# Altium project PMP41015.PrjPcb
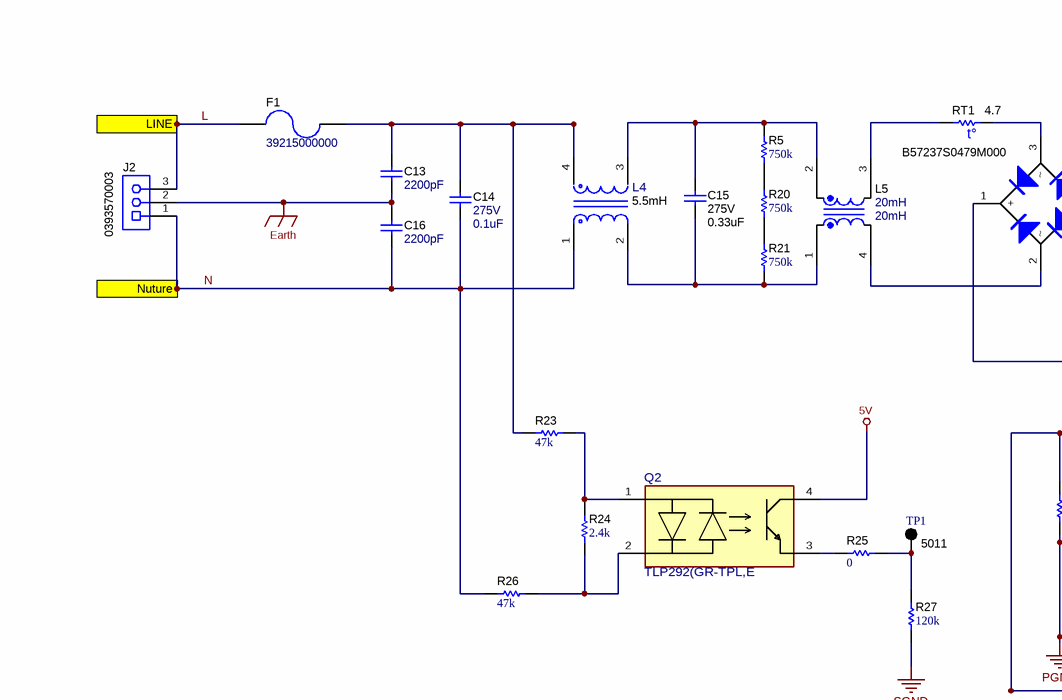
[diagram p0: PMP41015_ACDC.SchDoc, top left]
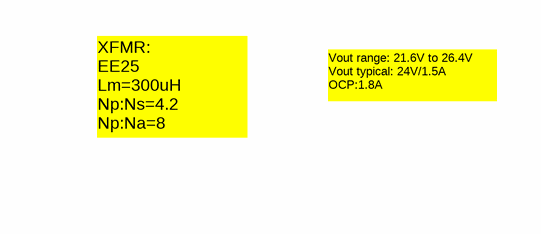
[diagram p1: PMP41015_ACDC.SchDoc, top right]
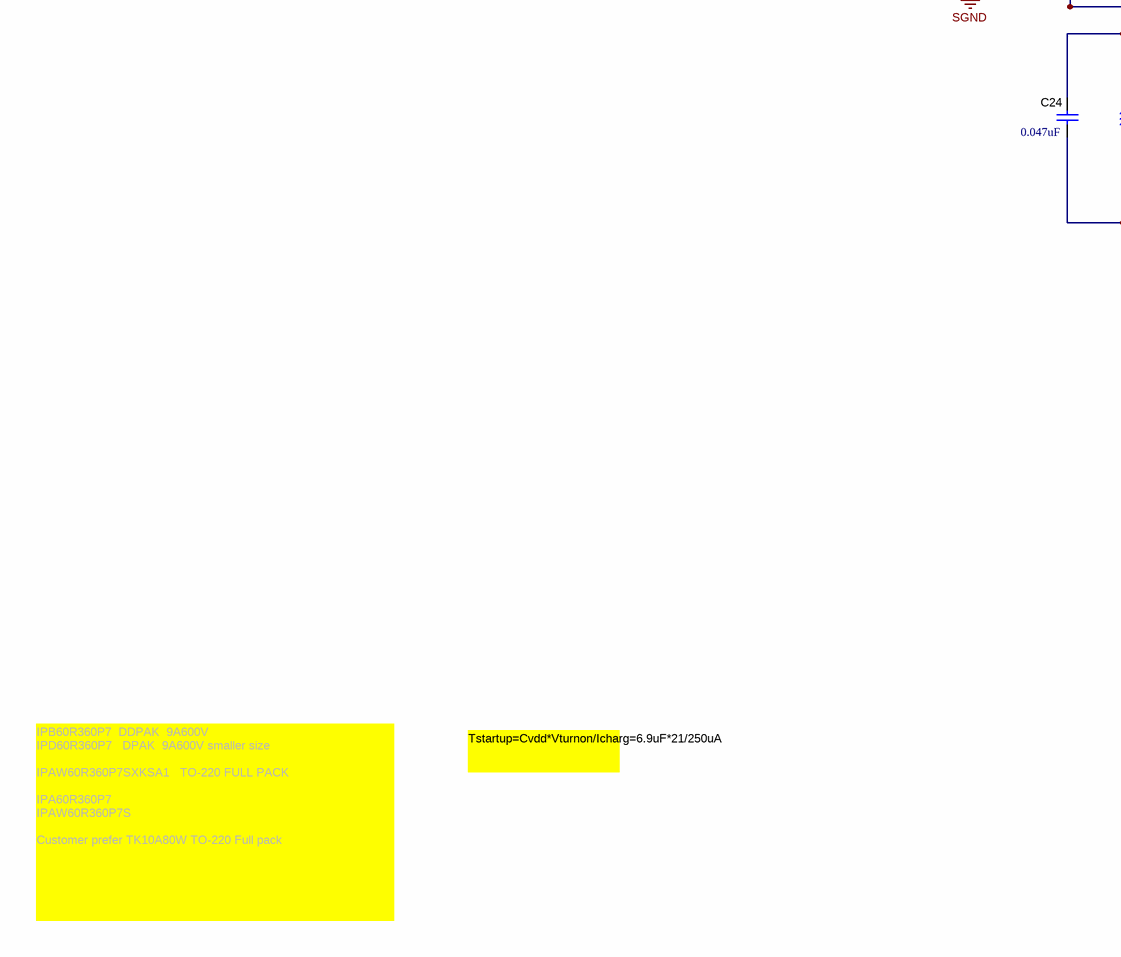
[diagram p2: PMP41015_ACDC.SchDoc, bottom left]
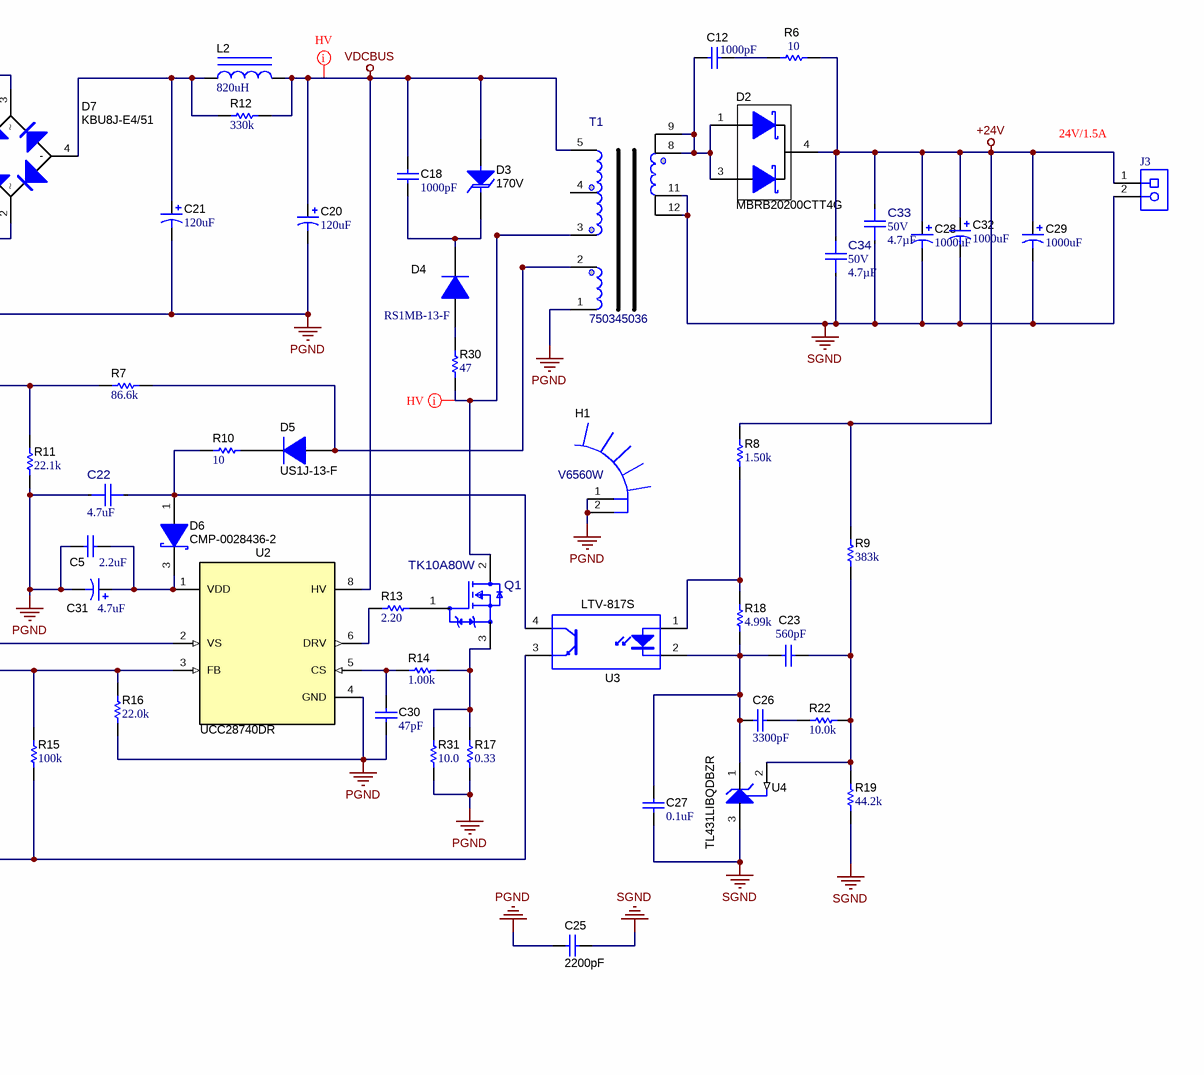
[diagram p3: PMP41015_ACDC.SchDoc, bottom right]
CopyrightYear: 2018; PCB_Layout: Max Wang; PCB_Rev: E1; PRJ_Customer: Public Release; PRJ_Engineer: Max Wang; PRJ_Number: PMP41015; PRJ_Title: PMP41015; SCH_Rev: E1; TechSupport: http://www.ti.com/support; TID: N/A
2 sheets, 89 parts. Net scope: flat (ports and power ports of the same name join across sheets).
Board file: PMP41015.PcbDoc
Sheets:
  PMP41015_ACDC.SchDoc
  PMP41015_DCDC.SchDoc

## Sheet PMP41015_ACDC.SchDoc
size 431 x 279 mm; Date: Not shown in title block; ApprovedBy: Not shown in title block; CheckedBy: Not shown in title block; Author: Max Wang; CompanyName: Not shown in title block; DrawnBy: Max Wang; Engineer: Not shown in title block; Organization: Not shown in title block; Address1: Not shown in title block; Address2: Not shown in title block; Address3: Not shown in title block; Address4: Not shown in title block; DocumentNumber: 2; Revision: Use project parameter SCH_Rev; SheetNumber: 1; SheetTotal: 2; PageSetup: Record=PageOptions¦CenterHorizontal=True¦CenterVertical=True¦PrintScale=1.00¦XCorrection=1.00¦YCorrection=1.00¦PrintKind=0¦BorderSize=5000000¦LeftOffset=0¦BottomOffset=0¦Orientation=2¦PaperLength=1000¦PaperWidth=1000¦Scale=100¦PaperSource=15¦PrintQuality=600¦MediaType=1¦DitherType=10¦PaperKind=Letter¦PrintScaleMode=1

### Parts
C5  ValueDisplayed: 2.2uF  [0805_HV]  (hidden comment: C2012X7R1H225K125AC)
C12  ValueDisplayed: 1000pF  [0805_HV]  (hidden comment: CMP-0007712-2)
C13  ValueDisplayed: 2200pF  [VY2_900x500_5]  (hidden comment: VY2222M35Y5UG6TV5)
C14  VDC_V: 275V  ValueDisplayed: 0.1uF  [CAPRR1500W60L1750T550H1250]  (hidden comment: ECQ-U2A104ML)
C15  VDC_V: 275V  ValueDisplayed: 0.33uF  [CAPRR1500W80L1750T950H1750]  (hidden comment: ECQ-U2A334ML)
C16  ValueDisplayed: 2200pF  [VY2_900x500_5]  (hidden comment: VY2222M35Y5UG6TV5)
C18  ValueDisplayed: 1000pF  [1206]  (hidden comment: CMP-0008891-2)
C20  ValueDisplayed: 120uF  [Nichicon_2500x3000_Snap]  (hidden comment: CMP-0010099-2)
C21  ValueDisplayed: 120uF  [Nichicon_2500x3000_Snap]  (hidden comment: CMP-0010099-2)
C22  ValueDisplayed: 4.7uF  [FP-CGA4J1X7R1H475K125AC_0805-MFG]  (hidden comment: CGA4J1X7R1H475K125AC)
C23  ValueDisplayed: 560pF  [0603]  (hidden comment: 06035C561KAT2A)
C24  ValueDisplayed: 0.047uF  [0603]  (hidden comment: CMP-0007015-5)
C25  ValueDisplayed: 2200pF  [CD45_900x600x1300]  (hidden comment: CD45-E2GA222M-NKA)
C26  ValueDisplayed: 3300pF  [0603]  (hidden comment: C0603C332F5GACTU)
C27  ValueDisplayed: 0.1uF  [0603]  (hidden comment: CMP-0006752-5)
C28  ValueDisplayed: 1000uF  [Chemi-Con_1250x2000]  (hidden comment: ELXZ350ELL102MK25S)
C29  ValueDisplayed: 1000uF  [Chemi-Con_1250x2000]  (hidden comment: ELXZ350ELL102MK25S)
C30  ValueDisplayed: 47pF  [0603]  (hidden comment: CMP-0006939-4)
C31  ValueDisplayed: 4.7uF  [SM_RADIAL_5MM]  (hidden comment: CMP-0011424-2)
C32  ValueDisplayed: 1000uF  [Chemi-Con_1250x2000]  (hidden comment: ELXZ350ELL102MK25S)
C33  VDC_V: 50V  Cap_F: 4.7µF  [FP-C2012X7R1H475K125AC_0805-MFG]  (hidden comment: C2012X7R1H475K125AC)
C34  VDC_V: 50V  Cap_F: 4.7µF  [FP-C2012X7R1H475K125AC_0805-MFG]  (hidden comment: C2012X7R1H475K125AC)
D2  MBRB20200CTT4G  [DDPAK]
D3  value 170V  [SMB]  (hidden comment: CMP-0005579-3)
D4  PartNumber: RS1MB-13-F  [SMB]  (hidden comment: CMP-0076889-2)
D5  US1J-13-F  [SMA]
D6  CMP-0028436-2  [SOT-23]
D7  KBU8J-E4/51  [KBU]
F1  39215000000  [FUSE_392]
H1  V6560W  [HSINK_V6560W]
J2  0393570003  [MOLEX_39357-0003]
J3  0393570002  [MOLEX_39357-0002]  (value not drawn)
L2  ValueDisplayed: 820uH  [WE-PD_1210]  (hidden comment: 7447709821)
L4  Ind_H: 5.5mH  [FP-750343092_PTH_14MM0_8MM89-0]  (hidden comment: 750343092)
L5  value 20mH  [WE-CMB_M]  (hidden comment: 744823220)
Q1  TK10A80W  [FP-IPAW60R360P7SXKSA1_PG-TO220-3-MFG]
Q2  TLP292(GR-TPL,E  [FP-TLP292(GR-TPL,E_SO4-IPC_A]
R5  ValueDisplayed: 750k  [1206]  (hidden comment: CMP-0017156-3)
R6  ValueDisplayed: 10  [0805_HV]  (hidden comment: CMP-0020804-2)
R7  ValueDisplayed: 86.6k  [0603]  (hidden comment: CMP-0022628-4)
R8  ValueDisplayed: 1.50k  [0603]  (hidden comment: CMP-0022883-5)
R9  ValueDisplayed: 383k  [0603]  (hidden comment: CMP-0024170-3)
R10  ValueDisplayed: 10  [0603]  (hidden comment: CMP-0025703-4)
R11  ValueDisplayed: 22.1k  [0603]  (hidden comment: CMP-0022220-4)
R12  ValueDisplayed: 330k  [1206]  (hidden comment: CMP-0018656-3)
R13  ValueDisplayed: 2.20  [0603]  (hidden comment: ERJ-3RQF2R2V)
R14  ValueDisplayed: 1.00k  [0603]  (hidden comment: CMP-0022109-5)
R15  ValueDisplayed: 100k  [0603]  (hidden comment: CMP-0022735-5)
R16  ValueDisplayed: 22.0k  [0603]  (hidden comment: CMP-0022925-5)
R17  ValueDisplayed: 0.33  [1206]  (hidden comment: CMP-0017788-3)
R18  ValueDisplayed: 4.99k  [0603]  (hidden comment: CMP-0023354-3)
R19  ValueDisplayed: 44.2k  [0603]  (hidden comment: CMP-0023118-5)
R20  ValueDisplayed: 750k  [1206]  (hidden comment: CMP-0017156-3)
R21  ValueDisplayed: 750k  [1206]  (hidden comment: CMP-0017156-3)
R22  ValueDisplayed: 10.0k  [0603]  (hidden comment: CMP-0021998-4)
R23  ValueDisplayed: 47k  [PR02]  (hidden comment: CMP-0014401-2)
R24  ValueDisplayed: 2.4k  [0402]  (hidden comment: CMP-0026891-5)
R25  ValueDisplayed: 0  [0603]  (hidden comment: CMP-0025697-4)
R26  ValueDisplayed: 47k  [PR02]  (hidden comment: CMP-0014401-2)
R27  ValueDisplayed: 120k  [0402]  (hidden comment: CMP-0025983-3)
R30  ValueDisplayed: 47  [1206]  (hidden comment: CMP-0018687-3)
R31  ValueDisplayed: 10.0  [0805_HV]  (hidden comment: CMP-0020847-3)
RT1  B57237S0479M000  value 4.7  [S237]
T1  750345036  [EE28 from Customer]
TP1  5011  [Keystone5011]
U2  UCC28740DR  [D0007A_N]
U3  LTV-817S  [DIP254P762X350-4]
U4  TL431LIBQDBZR  [DBZ0003A_N]

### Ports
LINE (in), Nuture (in)

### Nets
5V: Q2.4(Collector)
+24V: C28.1(+) C29.1(+) C32.1(+) C33.2 C34.2 D2.4(K) J3.1 R6.2 R8.2 R9.2
Earth: C13.2 C16.1 J2.2
PGND: C5.2 C20.2(-) C21.2(-) C22.1 C25.1 C30.2 C31.2(-) D7.1(+) H1.1 H1.2 R11.1 R16.1 R17.1 R31.1 T1.1 U2.4(GND)
SGND: C25.2 C27.2 C28.2(-) C29.2(-) C32.2(-) C33.1 C34.1 J3.2 R19.1 R27.1 T1.11 T1.12 U4.3(ANODE)
VDCBUS: C18.1 C20.1(+) D3.2(A) L2.2 R12.2 T1.5 U2.8(HV)
L: F1.2 J2.3 ; port LINE
N: C14.2 C16.2 J2.1 L4.1 R26.1 ; port Nuture
NetC5_1: C5.1 C31.1(+) D6.3(K) U2.1(VDD)
NetC12_1: C12.1 D2.1(A) D2.3(A) T1.8 T1.9
NetC12_2: C12.2 R6.1
NetC13_1: C13.1 C14.1 F1.1 L4.4 R23.1
NetC15_1: C15.1 L4.3 L5.2 R5.2
NetC15_2: C15.2 L4.2 L5.1 R21.1
NetC18_2: C18.2 D3.1(K) D4.1(K)
NetC21_1: C21.1(+) D7.4(-) L2.1 R12.1
NetC22_2: C22.2 D6.1(A) R10.1 U3.4(C)
NetC23_1: C23.1 R9.1 R19.2 R22.2 U4.2(REF)
NetC23_2: C23.2 C26.2 C27.1 R18.1 U3.2(K) U4.1(CATHODE)
NetC24_1: C24.1 R15.2 R16.2 U2.3(FB)
NetC24_2: C24.2 R15.1 U3.3(E)
NetC26_1: C26.1 R22.1
NetC30_1: C30.1 R14.1 U2.5(CS)
NetD4_2: D4.2(A) R30.2
NetD5_1: D5.1(K) R10.2
NetD5_2: D5.2(A) R7.2 T1.2
NetD7_2: D7.2 L5.4
NetD7_3: D7.3 RT1.2
NetL5_3: L5.3 RT1.1
NetQ1_1: Q1.1(Gate) R13.2
NetQ1_2: Q1.2(Drain) R30.1 T1.3
NetQ1_3: Q1.3(Source) R14.2 R17.2 R31.2
NetQ2_1: Q2.1(Anode/Cathode) R23.2 R24.2
NetQ2_2: Q2.2(Cathode/Anode) R24.1 R26.2
NetQ2_3: Q2.3(Emitter) R25.1
NetR5_1: R5.1 R20.2
NetR7_1: R7.1 R11.2 U2.2(VS)
NetR8_1: R8.1 R18.2 U3.1(A)
NetR13_1: R13.1 U2.6(DRV)
NetR20_1: R20.1 R21.2
NetR25_2: R25.2 R27.2 TP1.1

Not connected (* = marked no-connect by the designer): T1 4

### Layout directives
net class HV BUS: NetQ1_2, VDCBUS

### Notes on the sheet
- Vout range: 21.6V to 26.4V
  Vout typical: 24V/1.5A
  OCP:1.8A
- XFMR:
  EE25
  Lm=300uH
  Np:Ns=4.2
  Np:Na=8
- (near J3) 24V/1.5A
- Tstartup=Cvdd*Vturnon/Icharg=6.9uF*21/250uA
- IPB60R360P7  DDPAK  9A600V
  IPD60R360P7   DPAK  9A600V smaller size
  IPAW60R360P7SXKSA1   TO-220 FULL PACK
  IPA60R360P7
  IPAW60R360P7S
  Customer prefer TK10A80W TO-220 Full pack

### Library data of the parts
C5 = CMP-0007877-2: CAP, CERM, 2.2 uF, 50 V, +/- 10%, X7R, 0805; Manufacturer: TDK; Polarized: N; Value: 2.2uF; U/M: EA; Cap_F: 2.2µF; ESR_ohm: 3.66m; Value1: 0.00366 ohm; VDC_V: 50V; IRMS_A: 3.4121A; TaMin_C: -55°C; TaMax_C: 125°C; Cap_Case: 0805; SizeArea_mm2: 2.5; SizeAreaWB_mm2: 6.75; SizeX_mm: 2; SizeY_mm: 1.25; SizeZ_mm: 1.45; AEC Category: Q200
C12 = CMP-0007712-2: CAP, CERM, 1000 pF, 630 V, +/- 5%, X7R, 0805; PartNumber: C0805C102JBRACTU; Manufacturer: Kemet; Polarized: N; Value: 1000pF; U/M: EA; Cap_F: 1nF; Value1: Unknown; VDC_V: 630V; TaMin_C: -55°C; TaMax_C: 125°C; Cap_Case: 0805; SizeArea_mm2: 2.5; SizeAreaWB_mm2: 6.75; SizeX_mm: 2; SizeY_mm: 1.25; SizeZ_mm: 1.45; AEC Category: Q200
C13 C16 = CMP-0080613-1: CAP, CERM, 2200 pF, X1 440 VAC/Y2 300 VAC, +/- 20%, Y5U, Body9x5mm; Manufacturer: Vishay-Bccomponents; TaMin_C: -40°C; Polarized: N; AC_Safety: X1Y2; SizeAreaWB_mm2: 77; U/M: EA; Value: 2200pF; TaMax_C: 125°C; VAC_Y: 300V; VAC_X: 440V; SizeZ_mm: 13; SizeX_mm: 9; SizeY_mm: 5; Cap_Case: 9x5mm; SizeArea_mm2: 45; Cap_F: 2.2nF; AEC Category: Q200
C14 = CMP-0012496-1: CAP, Film, 0.1 uF, 275 V, +/- 20%, TH; Manufacturer: Panasonic; TaMin_C: -40°C; Polarized: N; Value1: Unknown; U/M: EA; Value: 0.1uF; TaMax_C: 100°C; Cap_Case: Radial 17.5x5.5x12.5; Cap_F: 100nF; AEC Category: Q200
C15 = CMP-0012499-3: CAP, Film, 0.33 uF, 275 V, +/- 20%, TH; Manufacturer: Panasonic; TaMin_C: -40°C; Polarized: N; SizeAreaWB_mm2: 224.25; Value1: Unknown; Value: 0.33uF; TaMax_C: 100°C; SizeZ_mm: 18; SizeX_mm: 17.5; SizeY_mm: 9.5; Cap_Case: Radial,17.5x17.5x9.5mm; SizeArea_mm2: 166.25; Cap_F: 330nF; AEC Category: Q200
C18 = CMP-0008891-2: CAP, CERM, 1000 pF, 630 V, +/- 5%, U2J, 1206; PartNumber: GRM31A7U2J102JW31D; Manufacturer: MuRata; Polarized: N; Value: 1000pF; U/M: EA; Cap_F: 1nF; Value1: Unknown; VDC_V: 630V; TaMin_C: -55°C; TaMax_C: 125°C; SizeArea_mm2: 5.12; SizeAreaWB_mm2: 10.92; SizeX_mm: 3.2; SizeY_mm: 1.6; SizeZ_mm: 1.35; AEC Category: Q200
C20 C21 = CMP-0010099-2: CAP, AL, 120 uF, 450 V, +/- 20%, TH; PartNumber: LLS2W121MELA; Manufacturer: Nichicon; Polarized: Y; CompType: Capacitor; Value: 120uF; U/M: EA; Cap_F: 120µF; Value1: Unknown; VDC_V: 450V; IRMS_A: 1.09A; TaMin_C: -25°C; TaMax_C: 85°C; Cap_Case: 25x30mm; SizeAreaWB_mm2: 729; SizeArea_mm2: 625; SizeX_mm: 25; SizeZ_mm: 32; AEC Category: Q200; AEC Qualified: N
C22 = CMP-0090082-1: Cap Ceramic 4.7uF 50V X7R 10% Pad SMD 0805 +125°C Automotive T/R; Manufacturer: TDK Corporation; Value: 4.7µF; Tolerance_%: 0.1%; TempCo: 15%; SizeZ_mm: 1.45mm; AEC Qualified: Yes; AEC Grade: Grade 1
C23 = CMP-0006807-4: CAP, CERM, 560 pF, 50 V, +/- 10%, X7R, 0603; Manufacturer: AVX; Polarized: N; Value: 560pF; U/M: EA; Value1: Unknown; VDC_V: 50V; TaMin_C: -55°C; TaMax_C: 125°C; SizeArea_mm2: 1.28; SizeAreaWB_mm2: 4.68; SizeX_mm: 1.6; SizeY_mm: 0.8; SizeZ_mm: 1; AEC Category: Q200
C24 = CMP-0007015-5: CAP, CERM, 0.047 uF, 50 V, +/- 10%, X5R, 0603; PartNumber: C1608X5R1H473K080AA; Manufacturer: TDK; Polarized: N; U/M: EA; Cap_F: 47nF; ESR_ohm: 49.007m; Value1: 0.049007 ohm; VDC_V: 50V; IRMS_A: 767.528mA; TaMin_C: -55°C; TaMax_C: 85°C; SizeArea_mm2: 1.28; SizeAreaWB_mm2: 4.68; SizeX_mm: 1.6; SizeY_mm: 0.8; SizeZ_mm: 1; AEC Category: Q200
C25 = CMP-0009597-2: CAP, CERM, 2200 pF,  V, +/- 20%, E, D9xT6mm; Manufacturer: TDK; TaMin_C: -25°C; Polarized: N; SizeAreaWB_mm2: 101.2; Value1: Unknown; U/M: EA; Value: 2200pF; TaMax_C: 125°C; SizeZ_mm: 13; SizeX_mm: 10.65; SizeY_mm: 6; Cap_Case: 9x6x13mm; SizeArea_mm2: 63.9; Cap_F: 2.2nF; AEC Category: Q200
C26 = CMP-0081060-1: CAP, CERM, 3300 pF, 50 V,+/- 1%, C0G/NP0, 0603; Manufacturer: Kemet; Polarized: N; Value: 3300pF; U/M: EA; Cap_F: 3.3nF; VDC_V: 50V; TaMin_C: -55°C; TaMax_C: 125°C; SizeArea_mm2: 1.28; SizeAreaWB_mm2: 4.68; SizeX_mm: 1.6; SizeY_mm: 0.8; SizeZ_mm: 1; AEC Category: Q200; Green_Lifecycle: Active; Green_REACh: Passed
C27 = CMP-0006752-5: CAP, CERM, 0.1 uF, 25 V, +/- 5%, X7R, 0603; PartNumber: 06033C104JAT2A; Manufacturer: AVX; Polarized: N; Value: 0.1uF; U/M: EA; Cap_F: 100nF; ESR_ohm: 50m; Value1: 0.05 ohm; VDC_V: 25V; TaMin_C: -55°C; TaMax_C: 125°C; SizeArea_mm2: 1.28; SizeAreaWB_mm2: 4.68; SizeX_mm: 1.6; SizeY_mm: 0.8; SizeZ_mm: 1; AEC Category: Q200
C28 C29 C32 = CMP-0010484-2: CAP, AL, 1000 uF, 35 V, +/- 20%, AEC-Q200 Grade 2, TH; Manufacturer: Chemi-Con; Polarized: Y; CompType: Capacitor; Value: 1000uF; U/M: EA; Cap_F: 1mF; Value1: Unknown; VDC_V: 35V; IRMS_A: 1.95A; TaMin_C: -55°C; TaMax_C: 105°C; Cap_Case: 12.5x25mm; SizeAreaWB_mm2: 210.25; SizeArea_mm2: 156.25; SizeX_mm: 12.5; SizeZ_mm: 21.5; AEC Category: Q200; AEC Grade: 2
C30 = CMP-0006939-4: CAP, CERM, 47 pF, 50 V, +/- 5%, C0G/NP0, 0603; PartNumber: C0603C470J5GACTU; Manufacturer: Kemet; Polarized: N; Value: 47pF; U/M: EA; Value1: Unknown; VDC_V: 50V; TaMin_C: -55°C; TaMax_C: 125°C; SizeArea_mm2: 1.28; SizeAreaWB_mm2: 4.68; SizeX_mm: 1.6; SizeY_mm: 0.8; SizeZ_mm: 1; AEC Category: Q200
C31 = CMP-0011424-2: CAP, AL, 4.7 uF, 50 V, +/- 20%, 1.52 ohm, SMD; PartNumber: UUD1H4R7MCL1GS; Manufacturer: Nichicon; Polarized: Y; CompType: Capacitor; Value: 4.7uF; U/M: EA; Cap_F: 4.7µF; VDC_V: 50V; ESR_ohm: 1.52; IRMS_A: 85mA; TaMin_C: -55°C; TaMax_C: 105°C; Cap_Case: 5x5.8; SizeAreaWB_mm2: 58.4; SizeArea_mm2: 31.8; SizeX_mm: 6; SizeY_mm: 5.3; AEC Category: Q200
C33 C34 = CMP-0088943-1: 4.7µF ±10% 50V Ceramic Capacitor X7R 0805 (2012 Metric); Manufacturer: TDK; TempCo: 15%; AEC Qualified: No; ValueDisplayed: 4.7uF; SizeZ_mm: 1.5mm
D2 = CMP-0028500-1: Diode, Schottky, 200 V, 20 A, DDPAK; Manufacturer: ON Semiconductor; Io_A: 20A; Green_Lifecycle: Not Set; SizeAreaWB_mm2: 209.6992; Vr_V: 200V; Green_REACh: Incomplete; TJmax_C: 150°C; U/M: EA; Value: 200V; SizeZ_mm: 4.445; SizeX_mm: 15.245; SizeY_mm: 10.16; Vf_V: 1V; SizeArea_mm2: 154.8892; AEC Category: Q101; RJC_CperW: 2
D3 = CMP-0005579-3: Diode, TVS, Uni, 170 V, 275 Vc, SMB; PartNumber: SMBJ170A-13-F; Manufacturer: Diodes Inc.; Value1: 600W; SizeAreaWB_mm2: 44.156; SizeArea_mm2: 21.336; SizeX_mm: 5.6; SizeY_mm: 3.81; SizeZ_mm: 2.6; AEC Category: Q101; Vbr_Min: 189V; Vc: 275V; Ipp: 2.2A; Vbr_Max: 217.5V
D4 = CMP-0076889-2: Diode, P-N, 1000 V, 1 A, SMB; Manufacturer: Diodes Inc.; Vf_V: 1.3V; Value: 1000V; Value1: 1A; Vr_V: 1kV; TJmax_C: 150°C; RJC_CperW: 20.0; SizeAreaWB_mm2: 44.156; SizeArea_mm2: 21.336; SizeX_mm: 5.6; SizeY_mm: 3.81; SizeZ_mm: 2.6; AEC Category: Q101; Green_Lifecycle: Active; Green_REACh: Passed
D5 = CMP-0077027-2: Diode, Ultrafast, 600 V, 1 A, SMA; Manufacturer: Diodes Inc.; Vf_V: 1.7V; Value: 600V; Value1: 1A; TJmax_C: 150°C; SizeAreaWB_mm2: 37.3428; SizeArea_mm2: 16.3228; SizeX_mm: 5.59; SizeY_mm: 2.92; SizeZ_mm: 2.87; AEC Category: Q101; Green_Lifecycle: Active; Green_REACh: Passed
D6 = CMP-0028436-2: Diode, Schottky, 40 V, 0.2 A, SOT-23; PartNumber: BAS40-7-F; Manufacturer: Diodes Inc.; Vf_V: 800mV; Value: 40V; Value1: 0.2A; Value2: 0.8V; Io_A: 200mA; SizeAreaWB_mm2: 14; SizeArea_mm2: 7.5; SizeX_mm: 2.5; SizeY_mm: 3; SizeZ_mm: 1.1; AEC Category: Q101; Green_Lifecycle: Not Set; Green_REACh: Incomplete
D7 = CMP-0085999-1: Diode, Switching-Bridge, 600 V, 8 A, TH; Manufacturer: Vishay-Semiconductor; Value2: 1V; SizeX_mm: 23.2; SizeAreaWB_mm2: 223.02; SizeY_mm: 6.85; SizeZ_mm: 19.3; Value1: 8A; AEC Qualified: N; AEC Category: Q101; TJmax_C: 150°C; Vr_V: 600V; Value: 600V; SizeArea_mm2: 158.92
F1 = CMP-0003562-2: Fuse, 5 A, 250VAC/VDC, TH; Manufacturer: Littelfuse; Irating_A: 5A; VAC_V: 250V
H1 = CMP-0086362-1: Heat Sink TO-220; Manufacturer: Assman WSW
J2 = CMP-0055340-2: Terminal Block, 3.5 mm, 3x1, Tin, TH; Manufacturer: Molex; Green_Lifecycle: Not Set; Green_REACh: Incomplete; CNHeader: FALSE; CT: TRUE
J3 = CMP-0055341-2: Terminal Block, 3.5 mm, 2x1, Tin, TH; Manufacturer: Molex; Green_Lifecycle: Not Set; Green_REACh: Incomplete; CNHeader: FALSE; CT: TRUE
L2 = CMP-0064762-2: Inductor, Shielded Drum Core, Ferrite, 820 uH, 0.95 A, 1 ohm, SMD; Manufacturer: Wurth Elektronik; Isat: 1.1A @ 10% inductance drop; Irms: 0.95A @ 40C rise; Green_Lifecycle: Active; SizeAreaWB_mm2: 196; DCR_ohm: 1; Green_REACh: Passed; Value1: 1 ohm; Value: 820uH; Imax_A: 950mA; SizeZ_mm: 10; SizeX_mm: 12; Value2: 0.95A; SizeArea_mm2: 144; Ind_H: 820µH; AEC Category: Q200
L4 = CMP-0086690-2: Power Common Mode Choke; Manufacturer: Wurth Electronics; SizeZ_mm: 18.5mm; DCR_ohm: 0.04; AEC Qualified: No
L5 = CMP-0013122-1: Coupled inductor, 20 mH, 1.5 A, 0.27 ohm, TH; Manufacturer: Wurth Elektronik; SizeAreaWB_mm2: 513; DCR_ohm: 0.27; SizeZ_mm: 26.5; SizeX_mm: 25; SizeY_mm: 17; SizeArea_mm2: 425
Q1 = CMP-0086795-1: N-Channel 650V 9A (Tc) 22W (Tc) Through Hole PG-TO220 Full Pack; PartNumber: IPAW60R360P7SXKSA1; Manufacturer: Infineon; QgTyp_nC: 13nC @ 10V; Vgs_V: 20V; AEC Qualified: No; SizeZ_mm: 18.57mm; ChMode: False; Rdson45_ohm: 0.3
Q2 = CMP-0086019-2: OPTOISOLATOR 3.75KV TRANS 4-SO; Manufacturer: Toshiba; CTR (Max): 300%; CTR (Min): 100%; SizeZ_mm: 2.3mm
R5 R20 R21 = CMP-0017156-3: RES, 750 k, 1%, 0.25 W, AEC-Q200 Grade 0, 1206; PartNumber: CRCW1206750KFKEA; Manufacturer: Vishay-Dale; Value: 750k; Power_W: 250mW; Value2: 0.25W; VDC_V: 200V; TempCo: 100 ppm/C; SizeArea_mm2: 5.12; SizeX_mm: 3.2; SizeY_mm: 1.6; SizeZ_mm: 1.35; EIA_Code: E96; AEC Category: Q200; AEC Qualified: Y; AEC Grade: 0
R6 = CMP-0020804-2: RES, 10, 5%, 0.125 W, 0805; PartNumber: RC0805JR-0710RL; Manufacturer: Yageo America; Value: 10; Value_Code: 10R0; Power_W: 125mW; Value2: 0.125W; VDC_V: 150V; TempCo: 200 ppm/C; SizeArea_mm2: 2.5; SizeX_mm: 2; SizeY_mm: 1.25; SizeZ_mm: 1.45; EIA_Code: E24; U/M: EA; AEC Category: Q200
R7 = CMP-0022628-4: RES, 86.6 k, 1%, 0.1 W, AEC-Q200 Grade 0, 0603; PartNumber: CRCW060386K6FKEA; Manufacturer: Vishay-Dale; Value: 86.6k; Value_Code: 86k6; Power_W: 100mW; Value2: 0.1W; VDC_V: 75V; TempCo: 100 ppm/C; SizeArea_mm2: 1.28; SizeX_mm: 1.6; SizeY_mm: 0.8; SizeZ_mm: 1; EIA_Code: E96; AEC Category: Q200; AEC Qualified: Y; AEC Grade: 0
R8 = CMP-0022883-5: RES, 1.50 k, 1%, 0.1 W, 0603; PartNumber: RC0603FR-071K5L; Manufacturer: Yageo; Value: 1.50k; Res_ohm: 1.5k; Value_Code: 1k50; Power_W: 100mW; Value2: 0.1W; VDC_V: 75V; TempCo: 100 ppm/C; SizeArea_mm2: 1.28; SizeX_mm: 1.6; SizeY_mm: 0.8; SizeZ_mm: 1; EIA_Code: E96; AEC Category: Q200; AEC Qualified: N; SizeAreaWB_mm2: 4.68
R9 = CMP-0024170-3: RES, 383 k, 0.1%, 0.1 W, 0603; PartNumber: RT0603BRD07383KL; Manufacturer: Yageo America; Value: 383k; Power_W: 100mW; Value2: 0.1W; VDC_V: 75V; TempCo: 25 ppm/C; SizeArea_mm2: 1.28; SizeX_mm: 1.6; SizeY_mm: 0.8; SizeZ_mm: 1; EIA_Code: E192; U/M: EA; AEC Category: Q200
R10 = CMP-0025703-4: RES, 10, 5%, 0.1 W, AEC-Q200 Grade 0, 0603; PartNumber: CRCW060310R0JNEA; Manufacturer: Vishay-Dale; Value: 10; Value_Code: 10R0; Power_W: 100mW; Value2: 0.1W; VDC_V: 75V; TempCo: 200 ppm/C; SizeArea_mm2: 1.28; SizeX_mm: 1.6; SizeY_mm: 0.8; SizeZ_mm: 1; EIA_Code: E24; AEC Category: Q200; AEC Qualified: Y; AEC Grade: 0
R11 = CMP-0022220-4: RES, 22.1 k, 1%, 0.1 W, AEC-Q200 Grade 0, 0603; PartNumber: CRCW060322K1FKEA; Manufacturer: Vishay-Dale; Value: 22.1k; Value_Code: 22k1; Power_W: 100mW; Value2: 0.1W; VDC_V: 75V; TempCo: 100 ppm/C; SizeArea_mm2: 1.28; SizeX_mm: 1.6; SizeY_mm: 0.8; SizeZ_mm: 1; EIA_Code: E96; AEC Category: Q200; AEC Qualified: Y; AEC Grade: 0
R12 = CMP-0018656-3: RES, 330 k, 5%, 0.25 W, AEC-Q200 Grade 0, 1206; PartNumber: CRCW1206330KJNEA; Manufacturer: Vishay-Dale; Value: 330k; Power_W: 250mW; Value2: 0.25W; VDC_V: 200V; TempCo: 200 ppm/C; SizeArea_mm2: 5.12; SizeX_mm: 3.2; SizeY_mm: 1.6; SizeZ_mm: 1.35; EIA_Code: E24; AEC Category: Q200; AEC Qualified: Y; AEC Grade: 0
R13 = CMP-0022711-2: RES, 2.20, 1%, 0.1 W, 0603; Manufacturer: Panasonic; Value: 2.20; Res_ohm: 2.2; Value_Code: 2R20; Power_W: 100mW; Value2: 0.1W; TempCo: 200 ppm/C; SizeArea_mm2: 1.28; SizeX_mm: 1.6; SizeY_mm: 0.8; SizeZ_mm: 1; U/M: EA; AEC Category: Q200
R14 = CMP-0022109-5: RES, 1.00 k, 1%, 0.1 W, AEC-Q200 Grade 0, 0603; PartNumber: CRCW06031K00FKEA; Manufacturer: Vishay-Dale; Value: 1.00k; Res_ohm: 1k; Value_Code: 1k00; Power_W: 100mW; Value2: 0.1W; VDC_V: 75V; TempCo: 100 ppm/C; SizeArea_mm2: 1.28; SizeX_mm: 1.6; SizeY_mm: 0.8; SizeZ_mm: 1; EIA_Code: E96; AEC Category: Q200; AEC Qualified: Y; AEC Grade: 0
R15 = CMP-0022735-5: RES, 100 k, 1%, 0.1 W, 0603; PartNumber: RC0603FR-07100KL; Manufacturer: Yageo; Value: 100k; Power_W: 100mW; Value2: 0.1W; VDC_V: 75V; TempCo: 100 ppm/C; SizeArea_mm2: 1.28; SizeX_mm: 1.6; SizeY_mm: 0.8; SizeZ_mm: 1; EIA_Code: E96; AEC Category: Q200; AEC Qualified: N; SizeAreaWB_mm2: 4.68
R16 = CMP-0022925-5: RES, 22.0 k, 1%, 0.1 W, 0603; PartNumber: RC0603FR-0722KL; Manufacturer: Yageo; Value: 22.0k; Res_ohm: 22k; Value_Code: 22k0; Power_W: 100mW; Value2: 0.1W; VDC_V: 75V; TempCo: 100 ppm/C; SizeArea_mm2: 1.28; SizeX_mm: 1.6; SizeY_mm: 0.8; SizeZ_mm: 1; AEC Category: Q200; AEC Qualified: N; SizeAreaWB_mm2: 4.68
R17 = CMP-0017788-3: RES, 0.33, 1%, 0.25 W, AEC-Q200 Grade 0, 1206; PartNumber: ERJ-8RQFR33V; Manufacturer: Panasonic; Value: 0.33; Value_Code: R330; Power_W: 250mW; Value2: 0.25W; TempCo: 250 ppm/C; SizeArea_mm2: 5.12; SizeX_mm: 3.2; SizeY_mm: 1.6; SizeZ_mm: 1.35; EIA_Code: E96; AEC Category: Q200; AEC Qualified: Y; AEC Grade: 0; SizeAreaWB_mm2: 10.92
R18 = CMP-0023354-3: RES, 4.99 k, 0.1%, 0.063 W, 0603; PartNumber: CPF0603B4K99E; Manufacturer: TE Connectivity; Value: 4.99k; Value_Code: 4k99; Power_W: 63mW; Value2: 0.063W; VDC_V: 50V; TempCo: 25 ppm/C; SizeArea_mm2: 1.28; SizeX_mm: 1.6; SizeY_mm: 0.8; SizeZ_mm: 1; EIA_Code: E192; U/M: EA; AEC Category: Q200
R19 = CMP-0023118-5: RES, 44.2 k, 1%, 0.1 W, 0603; PartNumber: RC0603FR-0744K2L; Manufacturer: Yageo; Value: 44.2k; Value_Code: 44k2; Power_W: 100mW; Value2: 0.1W; VDC_V: 75V; TempCo: 100 ppm/C; SizeArea_mm2: 1.28; SizeX_mm: 1.6; SizeY_mm: 0.8; SizeZ_mm: 1; EIA_Code: E96; AEC Category: Q200; AEC Qualified: N; SizeAreaWB_mm2: 4.68
R22 = CMP-0021998-4: RES, 10.0 k, 1%, 0.1 W, AEC-Q200 Grade 0, 0603; PartNumber: CRCW060310K0FKEA; Manufacturer: Vishay-Dale; Value: 10.0k; Res_ohm: 10k; Value_Code: 10k0; Power_W: 100mW; Value2: 0.1W; VDC_V: 75V; TempCo: 100 ppm/C; SizeArea_mm2: 1.28; SizeX_mm: 1.6; SizeY_mm: 0.8; SizeZ_mm: 1; EIA_Code: E96; AEC Category: Q200; AEC Qualified: Y; AEC Grade: 0
R23 R26 = CMP-0014401-2: RES, 47 k, 5%, 2 W, AEC-Q200 Grade 0, Axial resistor; PartNumber: PR02000204702JR500; Manufacturer: Vishay-Bccomponents; Value: 47k; Value_Code: 47k0; Power_W: 2W; VDC_V: 500V; TempCo: 250 ppm/C; EIA_Code: E24; U/M: EA; AEC Category: Q200; AEC Qualified: Y; AEC Grade: 0
R24 = CMP-0026891-5: RES, 2.4 k, 5%, 0.063 W, AEC-Q200 Grade 0, 0402; PartNumber: CRCW04022K40JNED; Manufacturer: Vishay-Dale; Value: 2.4k; Value_Code: 2k40; Power_W: 63mW; Value2: 0.063W; VDC_V: 50V; TempCo: 200 ppm/C; SizeArea_mm2: 0.5; SizeX_mm: 1; SizeZ_mm: 0.6; EIA_Code: E24; AEC Category: Q200; AEC Qualified: Y; AEC Grade: 0
R25 = CMP-0025697-4: RES, 0, 5%, 0.1 W, AEC-Q200 Grade 0, 0603; PartNumber: CRCW06030000Z0EA; Manufacturer: Vishay-Dale; Value: 0; Value_Code: 0000; Power_W: 100mW; Value2: 0.1W; VDC_V: 75V; TempCo: 200 ppm/C; SizeArea_mm2: 1.28; SizeX_mm: 1.6; SizeY_mm: 0.8; SizeZ_mm: 1; EIA_Code: E24; AEC Category: Q200; AEC Qualified: Y
R27 = CMP-0025983-3: RES, 120 k, 1%, 0.063 W, AEC-Q200 Grade 0, 0402; PartNumber: CRCW0402120KFKED; Manufacturer: Vishay-Dale; Value: 120k; Power_W: 63mW; Value2: 0.063W; VDC_V: 50V; TempCo: 100 ppm/C; SizeArea_mm2: 0.5; SizeX_mm: 1; SizeZ_mm: 0.6; AEC Category: Q200; AEC Qualified: Y; AEC Grade: 0
R30 = CMP-0018687-3: RES, 47, 5%, 0.25 W, AEC-Q200 Grade 0, 1206; PartNumber: CRCW120647R0JNEA; Manufacturer: Vishay-Dale; Value: 47; Value_Code: 47R0; Power_W: 250mW; Value2: 0.25W; VDC_V: 200V; TempCo: 200 ppm/C; SizeArea_mm2: 5.12; SizeX_mm: 3.2; SizeY_mm: 1.6; SizeZ_mm: 1.35; EIA_Code: E24; AEC Category: Q200; AEC Qualified: Y; AEC Grade: 0
R31 = CMP-0020847-3: RES, 10.0, 1%, 0.125 W, AEC-Q200 Grade 0, 0805; PartNumber: CRCW080510R0FKEA; Manufacturer: Vishay-Dale; Value: 10.0; Res_ohm: 10; Value_Code: 10R0; Power_W: 125mW; Value2: 0.125W; VDC_V: 150V; TempCo: 100 ppm/C; SizeArea_mm2: 2.5; SizeX_mm: 2; SizeY_mm: 1.25; SizeZ_mm: 1.45; EIA_Code: E96; AEC Category: Q200; AEC Qualified: Y; AEC Grade: 0
RT1 = CMP-0002554-2: Thermistor NTC, 4.70 ohm, 20%, 15x7mm; Manufacturer: TDK; TaMax_C: 170°C; SizeX_mm: 15; SizeY_mm: 7.5; TaMin_C: -55°C; Power_W: 3.1W; SizeZ_mm: 47; SizeArea_mm2: 112.5; SizeAreaWB_mm2: 161.5; U/M: EA
T1 = ER28-17: 300uH, ER28-17,TH; Manufacturer: Wurth; SymbolCreator: Use LDAP id; SymbolVersion: use current date i.e. 2008-05-20
TP1 = CMP-0055148-1: Test Point, Multipurpose, Black, TH; Manufacturer: Keystone; CNHeader: FALSE; Green_Lifecycle: Active; Green_REACh: Passed; ContactFinish: Silver; CT: TRUE
U2 = CMP-0067235-2: Constant-Voltage, Constant-Current Flyback Controller Using Opto-Coupler Feedback, D0007A (SOIC-7); Alternate Manufacturer: Texas Instruments; SizeAreaWB_mm2: 55.2; U/M: EA; SizeZ_mm: 1.75; SizeX_mm: 6.0; SizeY_mm: 4.9; SizeArea_mm2: 29.4; CompType: IC; AEC Category: Q200; AEC Qualified: N
U3 = LTV-817S: Optocoupler, 5 kV, 50-600% CTR, SMT; Manufacturer: Lite-On; CTR (Min): 50%; CTR (Max): 600%; Voltage_Isolation_Vrms: 5000V; SizeAreaWB_mm2: 80.256; SizeArea_mm2: 46.736; SizeX_mm: 10.16; SizeY_mm: 4.6
U4 = CMP-0084725-1: Programmable Shunt Regulator with Optimized Reference Current, DBZ0003A (SOT-23-3); Manufacturer: Texas Instruments; SizeZ_mm: 1.12; CompType: IC; SizeX_mm: 2.5; SizeY_mm: 3; SizeAreaWB_mm2: 14; AEC Category: Q200; SizeArea_mm2: 7.5; AEC Qualified: N

## Sheet PMP41015_DCDC.SchDoc
size 431 x 279 mm; Date: Not shown in title block; ApprovedBy: Not shown in title block; CheckedBy: Not shown in title block; Author: Not shown in title block; CompanyName: Not shown in title block; Engineer: Not shown in title block; Organization: Not shown in title block; Address1: Not shown in title block; Address2: Not shown in title block; Address3: Not shown in title block; Address4: Not shown in title block; DocumentNumber: 2; Revision: Use project parameter SCH_Rev; SheetNumber: 2; SheetTotal: 2; PageSetup: Record=PageOptions¦CenterHorizontal=True¦CenterVertical=True¦PrintScale=1.00¦XCorrection=1.00¦YCorrection=1.00¦PrintKind=0¦BorderSize=5000000¦LeftOffset=0¦BottomOffset=0¦Orientation=2¦PaperLength=1000¦PaperWidth=1000¦Scale=100¦PaperSource=15¦PrintQuality=600¦MediaType=1¦DitherType=10¦PaperKind=Letter¦PrintScaleMode=1
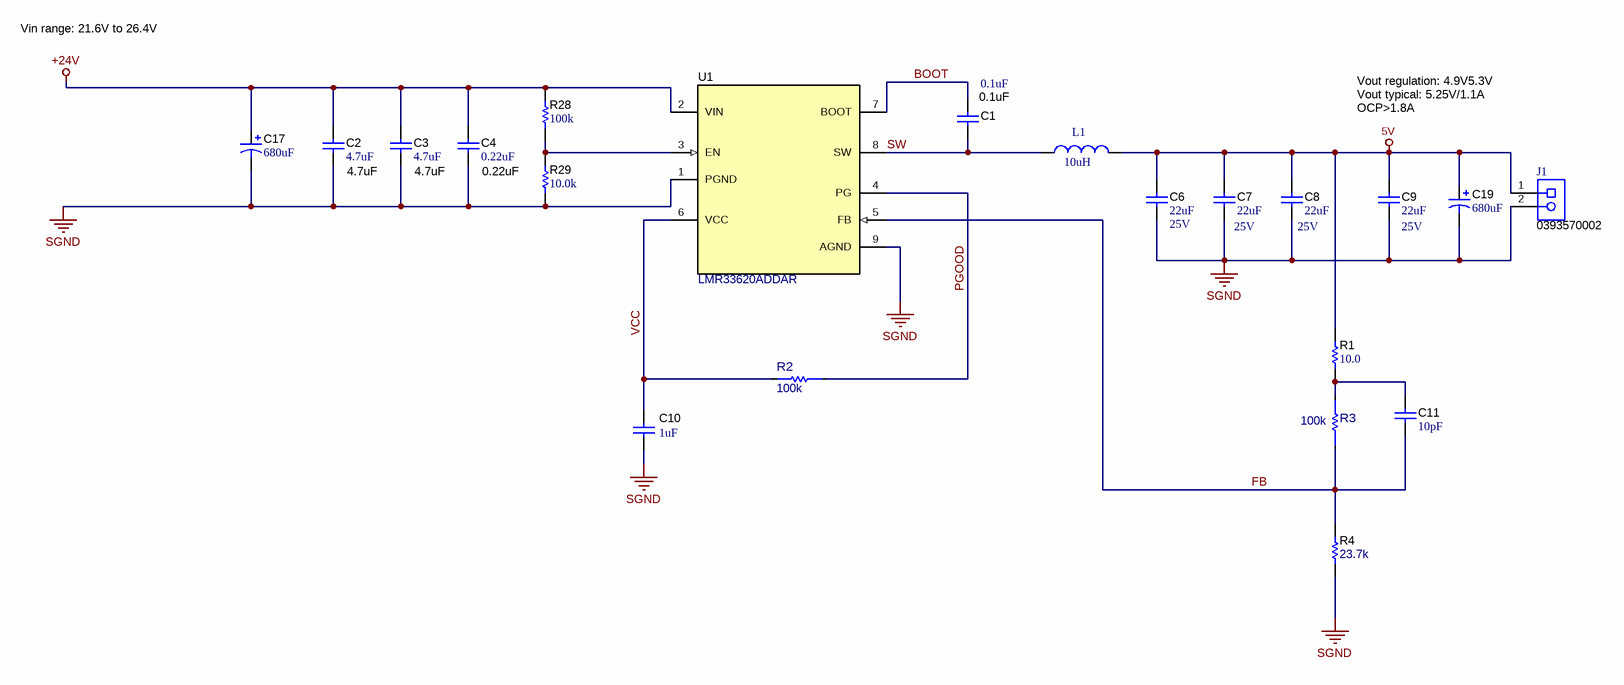
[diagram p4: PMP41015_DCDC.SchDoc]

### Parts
C1  0.1uF  [0603]
C2  4.7uF  [0805_HV]
C3  4.7uF  [0805_HV]
C4  0.22uF  [0603]
C6  ValueDisplayed: 22uF  VDC_V: 25V  [1210]
C7  ValueDisplayed: 22uF  VDC_V: 25V  [1210]  (hidden comment: CMP-0009169-2)
C8  ValueDisplayed: 22uF  VDC_V: 25V  [1210]  (hidden comment: CMP-0009169-2)
C9  ValueDisplayed: 22uF  VDC_V: 25V  [1210]  (hidden comment: CMP-0009169-2)
C10  ValueDisplayed: 1uF  [0603]  (hidden comment: CMP-0006833-4)
C11  ValueDisplayed: 10pF  [0402]  (hidden comment: CMP-0006207-2)
C17  ValueDisplayed: 680uF  [B41896_1250x2500]  (hidden comment: CMP-0010315-2)
C19  ValueDisplayed: 680uF  [CAPSMT_62_HA0]  (hidden comment: CMP-0010819-1)
J1  0393570002  [MOLEX_39357-0002]
L1  Inductance: 10uH  [WE-HCC_1090]
R1  ValueDisplayed: 10.0  [CPF0402]  (hidden comment: CMP-0026765-1)
R2  value 100k  [FP-CRCW0402100KFKEDC_0402-MFG]  (hidden comment: CRCW0402100KFKEDC)
R3  value 100k  [FP-CRCW0402100KFKEDC_0402-MFG]  (hidden comment: CRCW0402100KFKEDC)
R4  ValueDisplayed: 23.7k  [0201]  (hidden comment: RC0201FR-0723K7L)
R28  ValueDisplayed: 100k  [0603]  (hidden comment: CMP-0021990-4)
R29  ValueDisplayed: 10.0k  [0603]  (hidden comment: CMP-0022746-5)
U1  LMR33620ADDAR  [DDA0008J]

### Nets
5V: C6.1 C7.1 C8.1 C9.1 C19.1(+) J1.1 L1.2 R1.2
+24V: C2.1 C3.1 C4.1 C17.1(+) R28.2 U1.2(VIN)
SGND: C2.2 C3.2 C4.2 C6.2 C7.2 C8.2 C9.2 C10.2 C17.2(-) C19.2(-) J1.2 R4.1 R29.1 U1.1(PGND) U1.9(AGND)
BOOT: C1.1 U1.7(BOOT)
FB: C11.2 R3.1 R4.2 U1.5(FB)
PGOOD: R2.1 U1.4(PG)
SW: C1.2 L1.1 U1.8(SW)
VCC: C10.1 R2.2 U1.6(VCC)
NetC11_1: C11.1 R1.1 R3.2
NetR28_1: R28.1 R29.2 U1.3(EN)

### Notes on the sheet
- Vin range: 21.6V to 26.4V
- Vout regulation: 4.9V5.3V
  Vout typical: 5.25V/1.1A
  OCP>1.8A

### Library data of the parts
C1 = CMP-0006753-4: CAP, CERM, 0.1 uF, 25 V, +/- 10%, X7R, 0603; PartNumber: 06033C104KAT2A; Manufacturer: AVX; Polarized: N; U/M: EA; Cap_F: 100nF; ESR_ohm: 50m; Value1: 0.05 ohm; VDC_V: 25V; TaMin_C: -55°C; TaMax_C: 125°C; SizeArea_mm2: 1.28; SizeAreaWB_mm2: 4.68; SizeX_mm: 1.6; SizeY_mm: 0.8; SizeZ_mm: 1; AEC Category: Q200
C2 C3 = CMP-0007840-2: CAP, CERM, 4.7 uF, 50 V, +/- 10%, X5R, 0805; PartNumber: C2012X5R1H475K125AB; Manufacturer: TDK; Polarized: N; U/M: EA; Cap_F: 4.7µF; ESR_ohm: 2.346m; Value1: 0.002346 ohm; VDC_V: 50V; IRMS_A: 4.2602A; TaMin_C: -55°C; TaMax_C: 85°C; Cap_Case: 0805; SizeArea_mm2: 2.5; SizeAreaWB_mm2: 6.75; SizeX_mm: 2; SizeY_mm: 1.25; SizeZ_mm: 1.45; AEC Category: Q200
C4 = CMP-0007047-4: CAP, CERM, 0.22 uF, 50 V, +/- 10%, X7R, 0603; PartNumber: C1608X7R1H224K080AB; Manufacturer: TDK; Polarized: N; U/M: EA; Cap_F: 220nF; ESR_ohm: 21.699m; Value1: 0.021699 ohm; VDC_V: 50V; IRMS_A: 1.125A; TaMin_C: -55°C; TaMax_C: 125°C; SizeArea_mm2: 1.28; SizeAreaWB_mm2: 4.68; SizeX_mm: 1.6; SizeY_mm: 0.8; SizeZ_mm: 1; AEC Category: Q200
C6-C9 = CMP-0009169-2: CAP, CERM, 22 uF, 25 V, +/- 10%, X5R, 1210; PartNumber: CL32A226KAJNNNE; Manufacturer: Samsung Electro-Mechanics; Polarized: N; Value: 22uF; U/M: EA; Cap_F: 22µF; Value1: Unknown; TaMin_C: -55°C; TaMax_C: 85°C; SizeArea_mm2: 8; SizeAreaWB_mm2: 14.7; SizeX_mm: 3.2; SizeY_mm: 2.5; SizeZ_mm: 1.35; AEC Category: Q200
C10 = CMP-0006833-4: CAP, CERM, 1 uF, 25 V, +/- 10%, X7R, 0603; PartNumber: 885012206076; Manufacturer: Wurth Elektronik; Polarized: N; Value: 1uF; U/M: EA; Cap_F: 1µF; Value1: Unknown; VDC_V: 25V; TaMin_C: -55°C; TaMax_C: 125°C; SizeArea_mm2: 1.28; SizeAreaWB_mm2: 4.68; SizeX_mm: 1.6; SizeY_mm: 0.8; SizeZ_mm: 1; AEC Category: Q200
C11 = CMP-0006207-2: CAP, CERM, 10 pF, 50 V, +/- 5%, C0G/NP0, 0402; PartNumber: 500R07S100JV4T; Manufacturer: Johanson Technology; Polarized: N; Value: 10pF; U/M: EA; Value1: Unknown; VDC_V: 50V; TaMin_C: -55°C; TaMax_C: 125°C; SizeArea_mm2: 0.5; SizeAreaWB_mm2: 3; SizeX_mm: 1; SizeZ_mm: 0.6; AEC Category: Q200
C17 = CMP-0010315-2: CAP, AL, 680 uF, 35 V, +/- 20%, 0.041 ohm, AEC-Q200 Grade 1, TH; PartNumber: B41896C7687M000; Manufacturer: TDK; Polarized: Y; CompType: Capacitor; Value: 680uF; U/M: EA; Cap_F: 680µF; VDC_V: 35V; ESR_ohm: 41m; IRMS_A: 2.28A; TaMin_C: -55°C; TaMax_C: 125°C; Cap_Case: 12.5x25mm; SizeAreaWB_mm2: 210.25; SizeArea_mm2: 156.25; SizeX_mm: 12.5; SizeZ_mm: 27; AEC Category: Q200; AEC Grade: 1
C19 = CMP-0010819-1: CAP, AL, 680 uF, 6.3 V, +/- 20%, SMD; PartNumber: EMVA6R3ADA681MHA0G; Manufacturer: Chemi-Con; Polarized: Y; CompType: Capacitor; Value: 680uF; U/M: EA; Cap_F: 680µF; Value1: Unknown; VDC_V: 6.3V; IRMS_A: 290mA; TaMin_C: -40°C; TaMax_C: 85°C; Cap_Case: HA0; SizeAreaWB_mm2: 106.09; SizeArea_mm2: 68.89; SizeX_mm: 8.3; SizeZ_mm: 10; AEC Category: Q200
J1 = CMP-0055341-2: as J3 on sheet PMP41015_ACDC
L1 = CMP-0098714-1: WE-HCC SMT High Current Cube Inductor, size 1090, 10uH, 9A, 23.1mOhm; Manufacturer: Wurth Elektronik; Manufacturer Part Number: 7443331000; Material: Ferrite; Case/Size Code: 1090; DC Resistance: 22.75mOhm; Rated Inductance: 5.5uH; Saturation Current: 11.7A; Self Resonant Frequency: 35MHz
R1 = CMP-0026765-1: RES, 10.0, 0.1%, 0.063 W, 0402; PartNumber: CPF0402B10RE1; Manufacturer: TE Connectivity; Value: 10.0; Res_ohm: 10; Value_Code: 10R0; Power_W: 63mW; Value2: 0.063W; TempCo: 25 ppm/C; SizeArea_mm2: 0.5; SizeX_mm: 1; SizeZ_mm: 0.35; EIA_Code: E192; U/M: EA; AEC Category: Q200; AEC Qualified: N
R2 = CMP-0092204-1: 100 kOhms ±1% 0.063W, 1/16W Chip Resistor 0402 (1005 Metric)  Thick Film; Manufacturer: Vishay; Power_W: 63mW; AEC Qualified: No; TempCo: 100ppm/°C; SizeZ_mm: 0.35mm; VDC_V: 50V; Parameter 1: DNP
R3 = CMP-0092204-1: 100 kOhms ±1% 0.063W, 1/16W Chip Resistor 0402 (1005 Metric)  Thick Film; Manufacturer: Vishay; Power_W: 63mW; AEC Qualified: No; TempCo: 100ppm/°C; SizeZ_mm: 0.35mm; VDC_V: 50V
R4 = CMP-0027506-1: RES, 23.7 k, 1%, 0.05 W, 0201; Manufacturer: Yageo America; Power_W: 50mW; TempCo: 200 ppm/C; Value_Code: 23k7; U/M: EA; Value: 23.7k; EIA_Code: E96; SizeX_mm: 0.6; SizeY_mm: 0.3; SizeZ_mm: 0.26; Value2: 0.05W; SizeArea_mm2: 0.18; AEC Qualified: N; VDC_V: 25V; AEC Category: Q200
R28 = CMP-0021990-4: RES, 100 k, 1%, 0.1 W, AEC-Q200 Grade 0, 0603; PartNumber: CRCW0603100KFKEA; Manufacturer: Vishay-Dale; Value: 100k; Power_W: 100mW; Value2: 0.1W; VDC_V: 75V; TempCo: 100 ppm/C; SizeArea_mm2: 1.28; SizeX_mm: 1.6; SizeY_mm: 0.8; SizeZ_mm: 1; EIA_Code: E96; AEC Category: Q200; AEC Qualified: Y; AEC Grade: 0
R29 = CMP-0022746-5: RES, 10.0 k, 1%, 0.1 W, 0603; PartNumber: RC0603FR-0710KL; Manufacturer: Yageo; Value: 10.0k; Res_ohm: 10k; Value_Code: 10k0; Power_W: 100mW; Value2: 0.1W; VDC_V: 75V; TempCo: 100 ppm/C; SizeArea_mm2: 1.28; SizeX_mm: 1.6; SizeY_mm: 0.8; SizeZ_mm: 1; EIA_Code: E96; AEC Category: Q200; AEC Qualified: N; SizeAreaWB_mm2: 4.68
U1 = CMP-0074756-2: 3.8V to 36V 3A/2A Synchronous Step-Down Voltage Regulator, DDA0008J (SOIC-8); Manufacturer: Texas Instruments; SizeX_mm: 5.99; SizeY_mm: 4.89; CompType: IC; SizeZ_mm: 1.7; SizeArea_mm2: 29.2911; SizeAreaWB_mm2: 55.0511; U/M: EA

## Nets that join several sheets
5V: PMP41015_ACDC (Q2.4), PMP41015_DCDC (8 pins)
+24V: PMP41015_ACDC (10 pins), PMP41015_DCDC (6 pins)
SGND: PMP41015_ACDC (13 pins), PMP41015_DCDC (15 pins)

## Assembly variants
001: not fitted C27 R2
